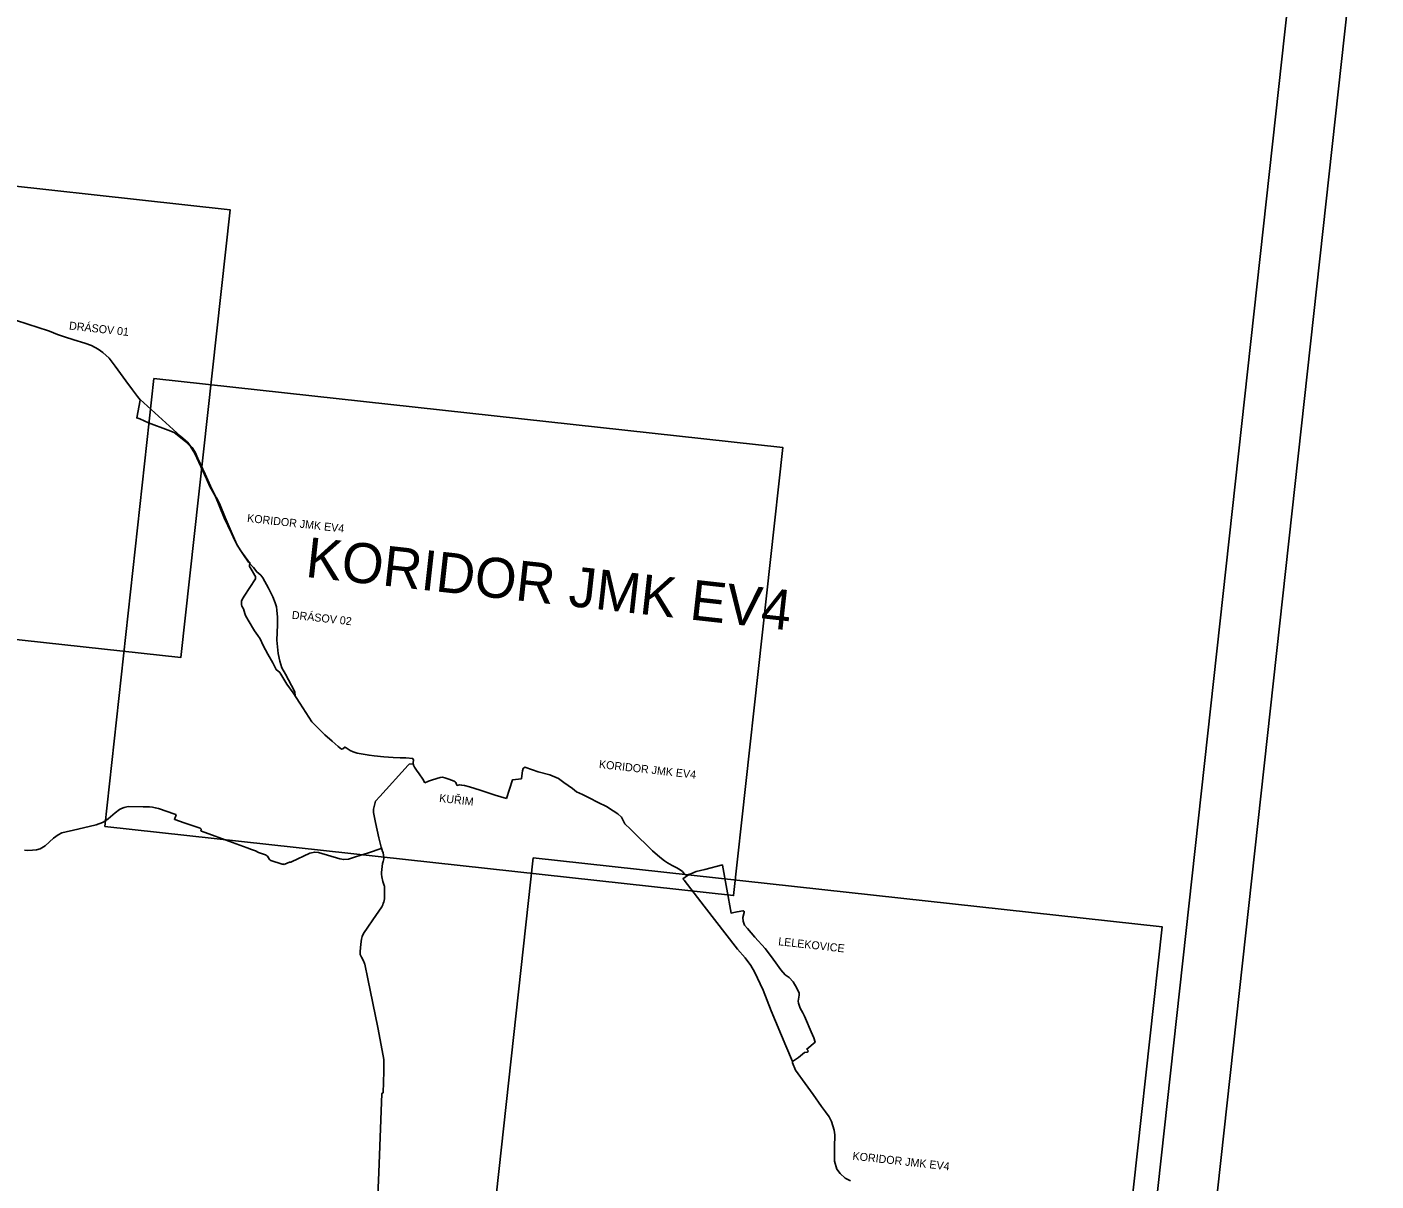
# Model space of a CAD drawing. Extents: x -678204 to -526855, y -1228851 to -1110393.
# Drawn here: x -605756 to -595642, y -1151538 to -1142888 of the extents above; entities that cross this region are included whole.
import ezdxf

# ---------------------------------------------------------------- set-up
doc = ezdxf.new("R2010")
doc.units = 0
for name, color, linetype in [('00_n_cyklo popisy', 7, 'Continuous'), ('00_n_cyklo popisy detaily', 7, 'Continuous'), ('00_n_cyklo provereni rekreacni hlavni', 7, 'Continuous'), ('00_n_cyklo provereni vedlejsi', 7, 'Continuous'), ('00_n_cyklo prujezdne podminecne rekreacni hlavni', 7, 'Continuous'), ('00_n_cyklo prujezdne rekreacni hlavni', 7, 'Continuous'), ('00_n_cyklo prujezdne rekreacni vedlejsi', 7, 'Continuous'), ('00_n_cyklo studie rekreacni vedlejsi', 7, 'Continuous'), ('00_n_cyklo trasovani rekreacni hlavni', 7, 'Continuous'), ('00_n_cyklo trasovani rekreacni vedlejsi', 7, 'Continuous'), ('_HELP', 7, 'Continuous'), ('_HELP BIG', 7, 'Continuous')]:
    doc.layers.add(name, color=color, linetype=linetype)

msp = doc.modelspace()

# ---------------------------------------------------------------- linework, layer by layer
at = {"layer": '00_n_cyklo provereni rekreacni hlavni'}
for points in [[(-604907, -1145683), (-604927, -1145657), (-604966, -1145607), (-605016, -1145540), (-605095, -1145430), (-605140, -1145371), (-605188, -1145329), (-605222, -1145302), (-605273, -1145276), (-605323, -1145257), (-605404, -1145233), (-605475, -1145210), (-605527, -1145192), (-605588, -1145167), (-605680, -1145139), (-605743, -1145117), (-605850, -1145083), (-606009, -1145032), (-606024, -1145027)], [(-604331, -1146425), (-604343, -1146407), (-604381, -1146329), (-604421, -1146241), (-604475, -1146122), (-604496, -1146076), (-604519, -1146041), (-604540, -1146014), (-604554, -1146000), (-604605, -1145956), (-604907, -1145681), (-604915, -1145672)], [(-604331, -1146425), (-604343, -1146407), (-604381, -1146329), (-604421, -1146241), (-604475, -1146122), (-604496, -1146076), (-604519, -1146041), (-604540, -1146014), (-604554, -1146000), (-604605, -1145956), (-604907, -1145681), (-604915, -1145672)], [(-604331, -1146425), (-604308, -1146472), (-604271, -1146565), (-604218, -1146687), (-604181, -1146773), (-604137, -1146838), (-604095, -1146899), (-604058, -1146939), (-604034, -1146972), (-604004, -1146997), (-603988, -1147016), (-603946, -1147095), (-603913, -1147160), (-603895, -1147204), (-603886, -1147233), (-603882, -1147258), (-603877, -1147312), (-603877, -1147334), (-603879, -1147369), (-603883, -1147485), (-603874, -1147585), (-603861, -1147642), (-603854, -1147667), (-603846, -1147692), (-603817, -1147739), (-603774, -1147823), (-603748, -1147871), (-603746, -1147901)], [(-600016, -1150642), (-600067, -1150525), (-600176, -1150262), (-600237, -1150107), (-600302, -1149969), (-600330, -1149923), (-600372, -1149864), (-600428, -1149799), (-600678, -1149477), (-600830, -1149282), (-600838, -1149274), (-600797, -1149242)]]:
    msp.add_lwpolyline(points, dxfattribs=at)
at = {"layer": '00_n_cyklo provereni vedlejsi'}
for points in [[(-603101, -1149045), (-603195, -1149078), (-603292, -1149109), (-603345, -1149126), (-603381, -1149128), (-603411, -1149123), (-603570, -1149075), (-603599, -1149073), (-603635, -1149081), (-603773, -1149145), (-603778, -1149147)], [(-600542, -1149170), (-600542, -1149168), (-600673, -1149203), (-600740, -1149219), (-600780, -1149236), (-600797, -1149241)], [(-600385, -1149513), (-600388, -1149512), (-600432, -1149520), (-600457, -1149526), (-600477, -1149529), (-600542, -1149170)], [(-600016, -1150642), (-599973, -1150611), (-599926, -1150575), (-599908, -1150573), (-599900, -1150566), (-599903, -1150556), (-599910, -1150549), (-599846, -1150496), (-599857, -1150464), (-599876, -1150420), (-599920, -1150319), (-599927, -1150303), (-599940, -1150277), (-599959, -1150243), (-599971, -1150205), (-599974, -1150190), (-599967, -1150145), (-599966, -1150129), (-599983, -1150093), (-600011, -1150046), (-600042, -1150013), (-600071, -1149992), (-600103, -1149956), (-600129, -1149920), (-600174, -1149858), (-600222, -1149795), (-600298, -1149711), (-600353, -1149645), (-600376, -1149619), (-600387, -1149590), (-600388, -1149562), (-600378, -1149526), (-600378, -1149517), (-600385, -1149513)]]:
    msp.add_lwpolyline(points, dxfattribs=at)
at = {"layer": '00_n_cyklo prujezdne podminecne rekreacni hlavni'}
msp.add_line((-602245, -1148646), (-602162, -1148672), dxfattribs=at)
for points in [[(-602245, -1148646), (-602358, -1148608), (-602439, -1148584), (-602475, -1148574), (-602498, -1148570), (-602514, -1148569), (-602530, -1148573), (-602533, -1148571), (-602540, -1148551), (-602545, -1148545), (-602554, -1148541), (-602594, -1148525), (-602623, -1148516), (-602641, -1148511), (-602659, -1148514), (-602715, -1148530), (-602746, -1148540), (-602774, -1148553)], [(-602048, -1148523), (-602117, -1148532), (-602162, -1148672)]]:
    msp.add_lwpolyline(points, dxfattribs=at)
at = {"layer": '00_n_cyklo prujezdne rekreacni hlavni'}
for points in [[(-604344, -1146408), (-604385, -1146332), (-604411, -1146274), (-604497, -1146085), (-604531, -1146032), (-604566, -1145998), (-604606, -1145966), (-604653, -1145927), (-604698, -1145909), (-604845, -1145854), (-604910, -1145826), (-604933, -1145818), (-604908, -1145686)], [(-604908, -1145686), (-604907, -1145683)], [(-604089, -1146923), (-604085, -1146909), (-604086, -1146903), (-604098, -1146889), (-604120, -1146860), (-604153, -1146814), (-604183, -1146768), (-604211, -1146709), (-604222, -1146683), (-604277, -1146567), (-604344, -1146408)], [(-602774, -1148553), (-602788, -1148526), (-602815, -1148487), (-602836, -1148458), (-602851, -1148437), (-602859, -1148420), (-602860, -1148401), (-602859, -1148383), (-602864, -1148371), (-602915, -1148366), (-602959, -1148366), (-603012, -1148363), (-603080, -1148359), (-603152, -1148352), (-603191, -1148346), (-603281, -1148330), (-603311, -1148321), (-603332, -1148311), (-603362, -1148292), (-603373, -1148286), (-603388, -1148298), (-603398, -1148301), (-603423, -1148281), (-603469, -1148240), (-603524, -1148193), (-603621, -1148097), (-603710, -1147956), (-603760, -1147879), (-603809, -1147815), (-603860, -1147727), (-603888, -1147704), (-603914, -1147654), (-603950, -1147589), (-603985, -1147524), (-604007, -1147474), (-604025, -1147449), (-604050, -1147414), (-604099, -1147333), (-604118, -1147298), (-604124, -1147284), (-604133, -1147249), (-604145, -1147229), (-604147, -1147217), (-604149, -1147204), (-604147, -1147191), (-604143, -1147179), (-604128, -1147154), (-604043, -1147025), (-604042, -1147021), (-604042, -1147016), (-604043, -1147008), (-604047, -1146999), (-604069, -1146964), (-604084, -1146940), (-604089, -1146932), (-604089, -1146923)], [(-600797, -1149241), (-600800, -1149242), (-600817, -1149243), (-600827, -1149237), (-600841, -1149218), (-600859, -1149205), (-600885, -1149191), (-600918, -1149174), (-600955, -1149152), (-600976, -1149137), (-601012, -1149110), (-601067, -1149062), (-601110, -1149020), (-601173, -1148958), (-601231, -1148901), (-601274, -1148861), (-601300, -1148811), (-601327, -1148786), (-601362, -1148763), (-601411, -1148731), (-601473, -1148701), (-601541, -1148666), (-601590, -1148641), (-601635, -1148620), (-601667, -1148596), (-601732, -1148552), (-601770, -1148522), (-601836, -1148493), (-601924, -1148471), (-601966, -1148456), (-602023, -1148436), (-602035, -1148445), (-602042, -1148463), (-602046, -1148502), (-602048, -1148523)], [(-599581, -1151537), (-599621, -1151517), (-599660, -1151482), (-599684, -1151450), (-599701, -1151389), (-599702, -1151285), (-599700, -1151192), (-599704, -1151156), (-599725, -1151091), (-599742, -1151057), (-599770, -1151019), (-599800, -1150979), (-599861, -1150890), (-599922, -1150806), (-599994, -1150706), (-600016, -1150653), (-600016, -1150642)]]:
    msp.add_lwpolyline(points, dxfattribs=at)
at = {"layer": '00_n_cyklo prujezdne rekreacni vedlejsi'}
msp.add_lwpolyline([(-603778, -1149147), (-603783, -1149147), (-603786, -1149147), (-603789, -1149148), (-603823, -1149164), (-603827, -1149165), (-603834, -1149164), (-603843, -1149162), (-603927, -1149136), (-603932, -1149133), (-603937, -1149128), (-603954, -1149104), (-603961, -1149097), (-603969, -1149093), (-603999, -1149084), (-604021, -1149076), (-604044, -1149064), (-604058, -1149058), (-604073, -1149052), (-604105, -1149040), (-604216, -1149000), (-604449, -1148916), (-604451, -1148915), (-604452, -1148912), (-604450, -1148903), (-604451, -1148900), (-604452, -1148897), (-604457, -1148893), (-604577, -1148853), (-604649, -1148829), (-604651, -1148827), (-604639, -1148794), (-604640, -1148791), (-604648, -1148787), (-604770, -1148745), (-604794, -1148740), (-604816, -1148736), (-604838, -1148734), (-604884, -1148732), (-604994, -1148731), (-605008, -1148734), (-605028, -1148738), (-605047, -1148746), (-605063, -1148754), (-605095, -1148777), (-605147, -1148823), (-605172, -1148840), (-605189, -1148850), (-605238, -1148867), (-605374, -1148901), (-605494, -1148929), (-605523, -1148944), (-605558, -1148968), (-605621, -1149025), (-605658, -1149047), (-605685, -1149055), (-605714, -1149058), (-605751, -1149061), (-605775, -1149058)], dxfattribs=at)
at = {"layer": '00_n_cyklo studie rekreacni vedlejsi'}
for points in [[(-603143, -1148692), (-603111, -1148656), (-602899, -1148420), (-602892, -1148414), (-602867, -1148412), (-602861, -1148407)], [(-603097, -1149051), (-603102, -1149036), (-603119, -1148966), (-603144, -1148850), (-603159, -1148775), (-603159, -1148751), (-603143, -1148692)], [(-603089, -1149468), (-603085, -1149456), (-603082, -1149449), (-603077, -1149424), (-603076, -1149383), (-603075, -1149352), (-603075, -1149340), (-603077, -1149329), (-603078, -1149324), (-603088, -1149292), (-603097, -1149258), (-603097, -1149252), (-603099, -1149242), (-603098, -1149225), (-603090, -1149157), (-603087, -1149144), (-603082, -1149123), (-603081, -1149110), (-603081, -1149109), (-603081, -1149107), (-603083, -1149099), (-603087, -1149075), (-603090, -1149068), (-603097, -1149051)], [(-603086, -1150878), (-603081, -1150717), (-603080, -1150660), (-603082, -1150627), (-603086, -1150600), (-603126, -1150388), (-603201, -1150022), (-603223, -1149913), (-603225, -1149908), (-603232, -1149888), (-603249, -1149861), (-603257, -1149839), (-603259, -1149817), (-603253, -1149763), (-603247, -1149724), (-603243, -1149705), (-603232, -1149683), (-603200, -1149634), (-603162, -1149579), (-603097, -1149482), (-603089, -1149468)], [(-603086, -1150878), (-603097, -1150882), (-603118, -1151473), (-603133, -1151820), (-603146, -1152098)]]:
    msp.add_lwpolyline(points, dxfattribs=at)
at = {"layer": '00_n_cyklo trasovani rekreacni hlavni'}
msp.add_line((-602245, -1148646), (-602162, -1148672), dxfattribs=at)
for points in [[(-604907, -1145683), (-604927, -1145657), (-604966, -1145607), (-605016, -1145540), (-605095, -1145430), (-605140, -1145371), (-605188, -1145329), (-605222, -1145302), (-605273, -1145276), (-605323, -1145257), (-605404, -1145233), (-605475, -1145210), (-605527, -1145192), (-605588, -1145167), (-605680, -1145139), (-605743, -1145117), (-605850, -1145083), (-606009, -1145032), (-606024, -1145027)], [(-604331, -1146425), (-604343, -1146407), (-604381, -1146329), (-604421, -1146241), (-604475, -1146122), (-604496, -1146076), (-604519, -1146041), (-604540, -1146014), (-604554, -1146000), (-604605, -1145956), (-604907, -1145681), (-604915, -1145672)], [(-604331, -1146425), (-604343, -1146407), (-604381, -1146329), (-604421, -1146241), (-604475, -1146122), (-604496, -1146076), (-604519, -1146041), (-604540, -1146014), (-604554, -1146000), (-604605, -1145956), (-604907, -1145681), (-604915, -1145672)], [(-604344, -1146408), (-604385, -1146332), (-604411, -1146274), (-604497, -1146085), (-604531, -1146032), (-604566, -1145998), (-604606, -1145966), (-604653, -1145927), (-604698, -1145909), (-604845, -1145854), (-604910, -1145826), (-604933, -1145818), (-604908, -1145686)], [(-604908, -1145686), (-604907, -1145683)], [(-604089, -1146923), (-604085, -1146909), (-604086, -1146903), (-604098, -1146889), (-604120, -1146860), (-604153, -1146814), (-604183, -1146768), (-604211, -1146709), (-604222, -1146683), (-604277, -1146567), (-604344, -1146408)], [(-604331, -1146425), (-604308, -1146472), (-604271, -1146565), (-604218, -1146687), (-604181, -1146773), (-604137, -1146838), (-604095, -1146899), (-604058, -1146939), (-604034, -1146972), (-604004, -1146997), (-603988, -1147016), (-603946, -1147095), (-603913, -1147160), (-603895, -1147204), (-603886, -1147233), (-603882, -1147258), (-603877, -1147312), (-603877, -1147334), (-603879, -1147369), (-603883, -1147485), (-603874, -1147585), (-603861, -1147642), (-603854, -1147667), (-603846, -1147692), (-603817, -1147739), (-603774, -1147823), (-603748, -1147871), (-603746, -1147901)], [(-602774, -1148553), (-602788, -1148526), (-602815, -1148487), (-602836, -1148458), (-602851, -1148437), (-602859, -1148420), (-602860, -1148401), (-602859, -1148383), (-602864, -1148371), (-602915, -1148366), (-602959, -1148366), (-603012, -1148363), (-603080, -1148359), (-603152, -1148352), (-603191, -1148346), (-603281, -1148330), (-603311, -1148321), (-603332, -1148311), (-603362, -1148292), (-603373, -1148286), (-603388, -1148298), (-603398, -1148301), (-603423, -1148281), (-603469, -1148240), (-603524, -1148193), (-603621, -1148097), (-603710, -1147956), (-603760, -1147879), (-603809, -1147815), (-603860, -1147727), (-603888, -1147704), (-603914, -1147654), (-603950, -1147589), (-603985, -1147524), (-604007, -1147474), (-604025, -1147449), (-604050, -1147414), (-604099, -1147333), (-604118, -1147298), (-604124, -1147284), (-604133, -1147249), (-604145, -1147229), (-604147, -1147217), (-604149, -1147204), (-604147, -1147191), (-604143, -1147179), (-604128, -1147154), (-604043, -1147025), (-604042, -1147021), (-604042, -1147016), (-604043, -1147008), (-604047, -1146999), (-604069, -1146964), (-604084, -1146940), (-604089, -1146932), (-604089, -1146923)], [(-602245, -1148646), (-602358, -1148608), (-602439, -1148584), (-602475, -1148574), (-602498, -1148570), (-602514, -1148569), (-602530, -1148573), (-602533, -1148571), (-602540, -1148551), (-602545, -1148545), (-602554, -1148541), (-602594, -1148525), (-602623, -1148516), (-602641, -1148511), (-602659, -1148514), (-602715, -1148530), (-602746, -1148540), (-602774, -1148553)], [(-600797, -1149241), (-600800, -1149242), (-600817, -1149243), (-600827, -1149237), (-600841, -1149218), (-600859, -1149205), (-600885, -1149191), (-600918, -1149174), (-600955, -1149152), (-600976, -1149137), (-601012, -1149110), (-601067, -1149062), (-601110, -1149020), (-601173, -1148958), (-601231, -1148901), (-601274, -1148861), (-601300, -1148811), (-601327, -1148786), (-601362, -1148763), (-601411, -1148731), (-601473, -1148701), (-601541, -1148666), (-601590, -1148641), (-601635, -1148620), (-601667, -1148596), (-601732, -1148552), (-601770, -1148522), (-601836, -1148493), (-601924, -1148471), (-601966, -1148456), (-602023, -1148436), (-602035, -1148445), (-602042, -1148463), (-602046, -1148502), (-602048, -1148523)], [(-602048, -1148523), (-602117, -1148532), (-602162, -1148672)], [(-600016, -1150642), (-600067, -1150525), (-600176, -1150262), (-600237, -1150107), (-600302, -1149969), (-600330, -1149923), (-600372, -1149864), (-600428, -1149799), (-600678, -1149477), (-600830, -1149282), (-600838, -1149274), (-600797, -1149242)], [(-599581, -1151537), (-599621, -1151517), (-599660, -1151482), (-599684, -1151450), (-599701, -1151389), (-599702, -1151285), (-599700, -1151192), (-599704, -1151156), (-599725, -1151091), (-599742, -1151057), (-599770, -1151019), (-599800, -1150979), (-599861, -1150890), (-599922, -1150806), (-599994, -1150706), (-600016, -1150653), (-600016, -1150642)]]:
    msp.add_lwpolyline(points, dxfattribs=at)
at = {"layer": '00_n_cyklo trasovani rekreacni vedlejsi'}
for points in [[(-603143, -1148692), (-603111, -1148656), (-602899, -1148420), (-602892, -1148414), (-602867, -1148412), (-602861, -1148407)], [(-603097, -1149051), (-603102, -1149036), (-603119, -1148966), (-603144, -1148850), (-603159, -1148775), (-603159, -1148751), (-603143, -1148692)], [(-603778, -1149147), (-603783, -1149147), (-603786, -1149147), (-603789, -1149148), (-603823, -1149164), (-603827, -1149165), (-603834, -1149164), (-603843, -1149162), (-603927, -1149136), (-603932, -1149133), (-603937, -1149128), (-603954, -1149104), (-603961, -1149097), (-603969, -1149093), (-603999, -1149084), (-604021, -1149076), (-604044, -1149064), (-604058, -1149058), (-604073, -1149052), (-604105, -1149040), (-604216, -1149000), (-604449, -1148916), (-604451, -1148915), (-604452, -1148912), (-604450, -1148903), (-604451, -1148900), (-604452, -1148897), (-604457, -1148893), (-604577, -1148853), (-604649, -1148829), (-604651, -1148827), (-604639, -1148794), (-604640, -1148791), (-604648, -1148787), (-604770, -1148745), (-604794, -1148740), (-604816, -1148736), (-604838, -1148734), (-604884, -1148732), (-604994, -1148731), (-605008, -1148734), (-605028, -1148738), (-605047, -1148746), (-605063, -1148754), (-605095, -1148777), (-605147, -1148823), (-605172, -1148840), (-605189, -1148850), (-605238, -1148867), (-605374, -1148901), (-605494, -1148929), (-605523, -1148944), (-605558, -1148968), (-605621, -1149025), (-605658, -1149047), (-605685, -1149055), (-605714, -1149058), (-605751, -1149061), (-605775, -1149058)], [(-603101, -1149045), (-603195, -1149078), (-603292, -1149109), (-603345, -1149126), (-603381, -1149128), (-603411, -1149123), (-603570, -1149075), (-603599, -1149073), (-603635, -1149081), (-603773, -1149145), (-603778, -1149147)], [(-603089, -1149468), (-603085, -1149456), (-603082, -1149449), (-603077, -1149424), (-603076, -1149383), (-603075, -1149352), (-603075, -1149340), (-603077, -1149329), (-603078, -1149324), (-603088, -1149292), (-603097, -1149258), (-603097, -1149252), (-603099, -1149242), (-603098, -1149225), (-603090, -1149157), (-603087, -1149144), (-603082, -1149123), (-603081, -1149110), (-603081, -1149109), (-603081, -1149107), (-603083, -1149099), (-603087, -1149075), (-603090, -1149068), (-603097, -1149051)], [(-600542, -1149170), (-600542, -1149168), (-600673, -1149203), (-600740, -1149219), (-600780, -1149236), (-600797, -1149241)], [(-600385, -1149513), (-600388, -1149512), (-600432, -1149520), (-600457, -1149526), (-600477, -1149529), (-600542, -1149170)], [(-603086, -1150878), (-603081, -1150717), (-603080, -1150660), (-603082, -1150627), (-603086, -1150600), (-603126, -1150388), (-603201, -1150022), (-603223, -1149913), (-603225, -1149908), (-603232, -1149888), (-603249, -1149861), (-603257, -1149839), (-603259, -1149817), (-603253, -1149763), (-603247, -1149724), (-603243, -1149705), (-603232, -1149683), (-603200, -1149634), (-603162, -1149579), (-603097, -1149482), (-603089, -1149468)], [(-600016, -1150642), (-599973, -1150611), (-599926, -1150575), (-599908, -1150573), (-599900, -1150566), (-599903, -1150556), (-599910, -1150549), (-599846, -1150496), (-599857, -1150464), (-599876, -1150420), (-599920, -1150319), (-599927, -1150303), (-599940, -1150277), (-599959, -1150243), (-599971, -1150205), (-599974, -1150190), (-599967, -1150145), (-599966, -1150129), (-599983, -1150093), (-600011, -1150046), (-600042, -1150013), (-600071, -1149992), (-600103, -1149956), (-600129, -1149920), (-600174, -1149858), (-600222, -1149795), (-600298, -1149711), (-600353, -1149645), (-600376, -1149619), (-600387, -1149590), (-600388, -1149562), (-600378, -1149526), (-600378, -1149517), (-600385, -1149513)], [(-603086, -1150878), (-603097, -1150882), (-603118, -1151473), (-603133, -1151820), (-603146, -1152098)]]:
    msp.add_lwpolyline(points, dxfattribs=at)
at = {"layer": '_HELP'}
for points in [[(-608949, -1143740), (-604234, -1144258), (-604603, -1147615), (-609318, -1147098)], [(-604804, -1145523), (-600089, -1146040), (-600458, -1149398), (-605172, -1148880)], [(-601960, -1149115), (-597246, -1149632), (-597614, -1152990), (-602329, -1152472)]]:
    msp.add_lwpolyline(points, close=True, dxfattribs=at)
at = {"layer": '_HELP BIG'}
for points in [[(-617877, -1157615), (-614771, -1129327), (-594626, -1131539), (-597732, -1159827)], [(-598180, -1159809), (-595074, -1131522), (-574929, -1133734), (-578035, -1162021)]]:
    msp.add_lwpolyline(points, close=True, dxfattribs=at)

# ---------------------------------------------------------------- texts
at = {"layer": '00_n_cyklo popisy'}
msp.add_text('KORIDOR JMK EV4', height=300, rotation=353.6836, dxfattribs=at).set_placement((-603675, -1147009))
at = {"layer": '00_n_cyklo popisy detaily'}
for s, p in [('DRÁSOV 01', (-605443, -1145155)), ('KORIDOR JMK EV4', (-604108, -1146597)), ('DRÁSOV 02', (-603773, -1147323)), ('KORIDOR JMK EV4', (-601470, -1148442)), ('KUŘIM', (-602668, -1148696)), ('LELEKOVICE', (-600126, -1149770)), ('KORIDOR JMK EV4', (-599569, -1151378))]:
    msp.add_text(s, height=60, rotation=353.6836, dxfattribs=at).set_placement(p)

doc.saveas('drawing.dxf')
